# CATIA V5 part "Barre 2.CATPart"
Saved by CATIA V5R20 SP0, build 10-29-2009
Part number: Barre 2
Bounding box of the stored display mesh (mm): x -169.748 to -149.748, y -391.857 to 68.143, z 0 to 10
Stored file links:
  C:\Users\Matthieu\Desktop\IFMA\Cours 2A\Thinkmotion\Projet_IAO_714_Matthieu_Perrusset\Barre 2.CATPart
  C:\Users\Matthieu\Desktop\IFMA\Cours 2A\Thinkmotion\Ass_skl_IAO.CATProduct
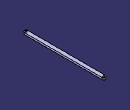
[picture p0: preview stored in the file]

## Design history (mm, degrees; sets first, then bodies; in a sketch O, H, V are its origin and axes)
AxisSystem1: origin (0, 0, 0), X (1, 0, 0), Y (0, 1, 0), Z (0, 0, 1)
Set1
  Plane1 "Plan_Ref": linked copy from another document
  Line1 "Axe_Pivot_b2b4": linked copy from another document
  Line2 "Barre_2": linked copy from another document
  Line3 "Axe_Pivot_b2b6": linked copy from another document
Body1 (main body)
  Sketch1 on Plane1, origin (0, 0, 0), H (1, 0, 0), V (0, 1, 0)
    line L1 (-169.7477, 58.1434) -> (-169.7477, -381.8566)
    arc A1 centre (-159.7477, -381.8566) radius 10 from (-169.7477, -381.8566) to (-149.7477, -381.8566) ccw
    point P3 (-159.7477, -381.8566)
    line L2 (-149.7477, -381.8566) -> (-149.7477, 58.1434)
    arc A2 centre (-159.7477, 58.1434) radius 10 from (-149.7477, 58.1434) to (-169.7477, 58.1434) ccw
    point P6 (-159.7477, 58.1434)
    reference projected point E1 (-159.7477, 58.1434) from Line1
    reference projected point E2 (-159.7477, 58.1434) from Line1
    reference projected line E3 (-159.7477, 58.1434) -> (-159.7477, -381.8566) from Line2
    reference projected line E4 (-159.7477, 58.1434) -> (-159.7477, -381.8566) from Line2
    reference projected line E5 (-159.7477, 58.1434) -> (-159.7477, -381.8566) from Line2
    reference projected line E6 (-159.7477, 58.1434) -> (-159.7477, -381.8566) from Line2
    reference projected point E7 (-159.7477, -381.8566) from Line3
    circle A3 centre (-159.7477, 58.1434) radius 5
    circle A4 centre (-159.7477, -381.8566) radius 5
    distance E2 A2 = 10
    distance L1 E5 = 10
    distance E6 L2 = 10
    distance P3 A1 = 10
    radius A3 = 5
    radius A4 = 5
    vertical: L1 V
    coincidence: E1 P6, E7 P3
    parallelism: L1 E3, E4 L2
  Pad1: profile Sketch1, direction (0, 0, 1), length 10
